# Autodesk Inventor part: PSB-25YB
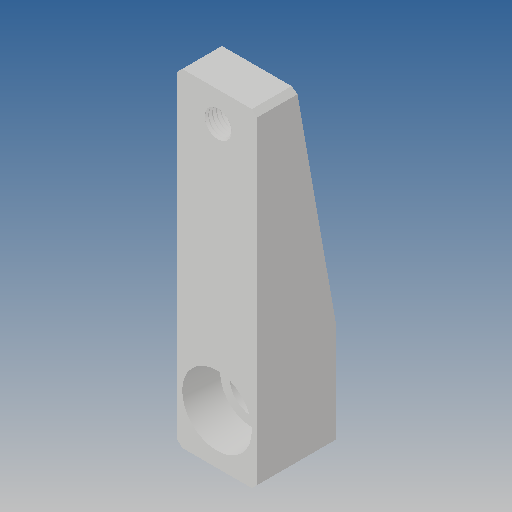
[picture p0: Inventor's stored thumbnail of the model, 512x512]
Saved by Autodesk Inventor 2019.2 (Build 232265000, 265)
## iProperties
Created: 2010-02
Part Number: PSB-25YB
Material: Ogólny
Document SubType Name: Modeling
Designer: CADENGINEERING4
Density: 1 g/cm^3
Appearance: Domyślna
Author: CADENGINEERING4
Revision Number: 1LAST_VERSION
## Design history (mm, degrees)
feature "Baza1"
node "Bryła1"
